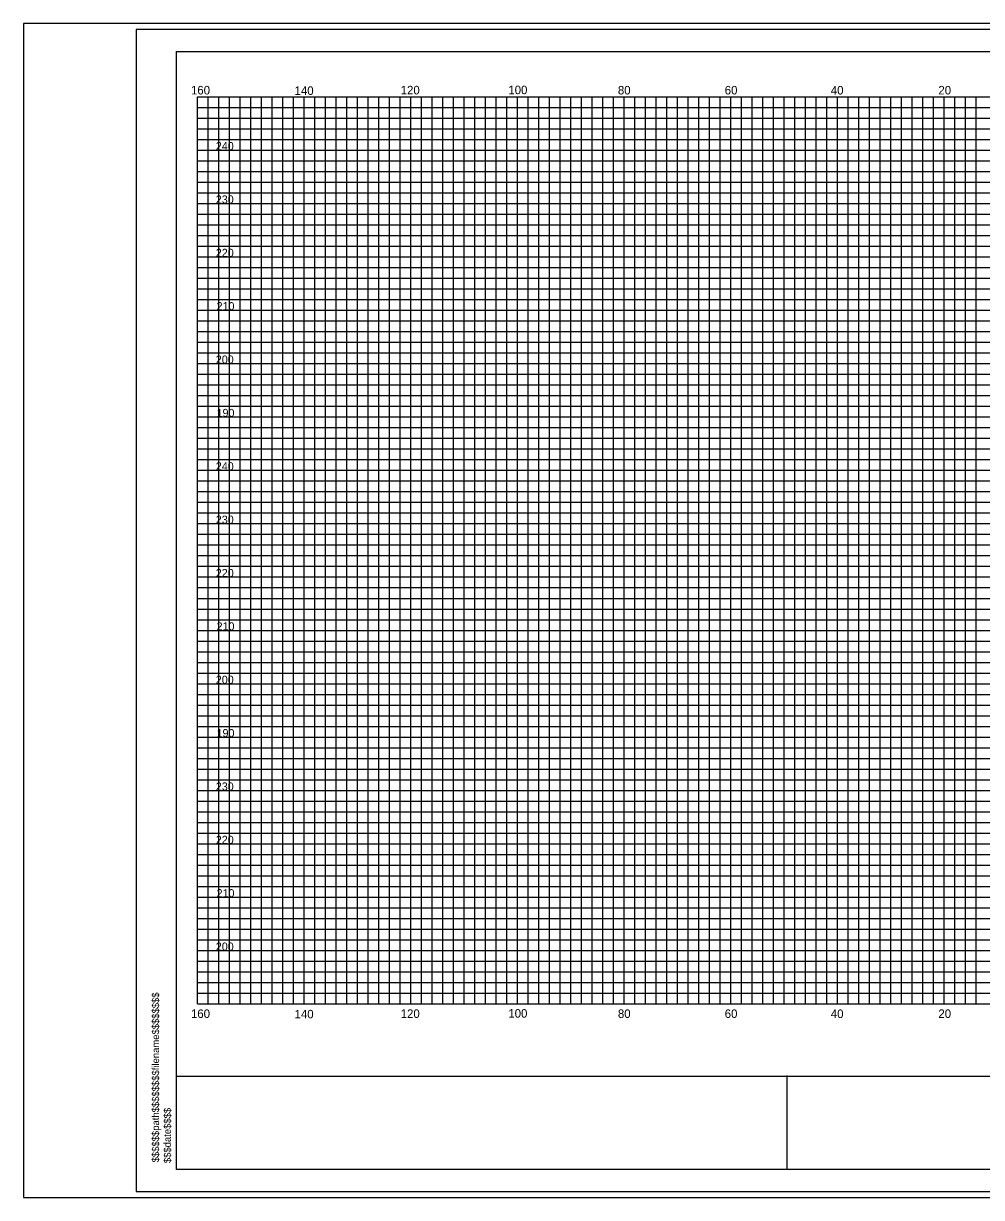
# Model space of a CAD drawing. Extents: x 967 to 1326, y 964 to 2304.
# Drawn here: x 967.4 to 1147, y 1243.7 to 1463.7 of the extents above; entities that cross this region are included whole.
import ezdxf

# ---------------------------------------------------------------- set-up
doc = ezdxf.new("R2010")
doc.units = 0
for name, color, linetype in [('Default', 7, 'Continuous'), ('RD_GPK_XS_Cell', 7, 'Continuous'), ('RD_PD_PaveShd', 7, 'Continuous'), ('RD_XS_ExGround', 7, 'Continuous'), ('RD_XS_ExPaveRet', 7, 'Continuous'), ('RD_XS_PaveOvlay', 7, 'Continuous'), ('RD_XS_TX_Elev_EX', 7, 'Continuous')]:
    doc.layers.add(name, color=color, linetype=linetype)

msp = doc.modelspace()

# ---------------------------------------------------------------- linework, layer by layer
at = {"layer": 'RD_GPK_XS_Cell'}
for p, q in [((1000, 1450), (1320, 1450)), ((1000, 1280), (1000, 1450)), ((1010, 1280), (1010, 1450)), ((1020, 1280), (1020, 1450)), ((1030, 1280), (1030, 1450)), ((1040, 1280), (1040, 1450)), ((1050, 1280), (1050, 1450)), ((1060, 1280), (1060, 1450)), ((1070, 1280), (1070, 1450)), ((1080, 1280), (1080, 1450)), ((1090, 1280), (1090, 1450)), ((1100, 1280), (1100, 1450)), ((1110, 1280), (1110, 1450)), ((1120, 1280), (1120, 1450)), ((1130, 1280), (1130, 1450)), ((1140, 1280), (1140, 1450)), ((1000, 1440), (1320, 1440)), ((1000, 1430), (1320, 1430)), ((1000, 1420), (1320, 1420)), ((1000, 1410), (1320, 1410)), ((1000, 1400), (1320, 1400)), ((1000, 1390), (1320, 1390)), ((1000, 1380), (1320, 1380)), ((1000, 1370), (1320, 1370)), ((1000, 1360), (1320, 1360)), ((1000, 1350), (1320, 1350)), ((1000, 1340), (1320, 1340)), ((1000, 1330), (1320, 1330)), ((1000, 1320), (1320, 1320)), ((1000, 1310), (1320, 1310)), ((1000, 1300), (1320, 1300)), ((1000, 1290), (1320, 1290)), ((1000, 1280), (1320, 1280))]:
    msp.add_line(p, q, dxfattribs=at)
at = {"layer": 'RD_PD_PaveShd'}
for p, q in [((996.11, 1248.98), (996.11, 1458.46)), ((996.11, 1458.46), (1323.89, 1458.46)), ((996.11, 1266.49), (1323.89, 1266.49)), ((1110.59, 1248.98), (1110.59, 1266.56)), ((1323.89, 1248.98), (996.11, 1248.98))]:
    msp.add_line(p, q, dxfattribs=at)
at = {"layer": 'RD_XS_ExGround'}
for p, q in [((1002, 1280), (1002, 1450)), ((1004, 1280), (1004, 1450)), ((1006, 1280), (1006, 1450)), ((1008, 1280), (1008, 1450)), ((1012, 1280), (1012, 1450)), ((1014, 1280), (1014, 1450)), ((1016, 1280), (1016, 1450)), ((1018, 1280), (1018, 1450)), ((1022, 1280), (1022, 1450)), ((1024, 1280), (1024, 1450)), ((1026, 1280), (1026, 1450)), ((1028, 1280), (1028, 1450)), ((1032, 1280), (1032, 1450)), ((1034, 1280), (1034, 1450)), ((1036, 1280), (1036, 1450)), ((1038, 1280), (1038, 1450)), ((1042, 1280), (1042, 1450)), ((1044, 1280), (1044, 1450)), ((1046, 1280), (1046, 1450)), ((1048, 1280), (1048, 1450)), ((1052, 1280), (1052, 1450)), ((1054, 1280), (1054, 1450)), ((1056, 1280), (1056, 1450)), ((1058, 1280), (1058, 1450)), ((1062, 1280), (1062, 1450)), ((1064, 1280), (1064, 1450)), ((1066, 1280), (1066, 1450)), ((1068, 1280), (1068, 1450)), ((1072, 1280), (1072, 1450)), ((1074, 1280), (1074, 1450)), ((1076, 1280), (1076, 1450)), ((1078, 1280), (1078, 1450)), ((1082, 1280), (1082, 1450)), ((1084, 1280), (1084, 1450)), ((1086, 1280), (1086, 1450)), ((1088, 1280), (1088, 1450)), ((1092, 1280), (1092, 1450)), ((1094, 1280), (1094, 1450)), ((1096, 1280), (1096, 1450)), ((1098, 1280), (1098, 1450)), ((1102, 1280), (1102, 1450)), ((1104, 1280), (1104, 1450)), ((1106, 1280), (1106, 1450)), ((1108, 1280), (1108, 1450)), ((1112, 1280), (1112, 1450)), ((1114, 1280), (1114, 1450)), ((1116, 1280), (1116, 1450)), ((1118, 1280), (1118, 1450)), ((1122, 1280), (1122, 1450)), ((1124, 1280), (1124, 1450)), ((1126, 1280), (1126, 1450)), ((1128, 1280), (1128, 1450)), ((1132, 1280), (1132, 1450)), ((1134, 1280), (1134, 1450)), ((1136, 1280), (1136, 1450)), ((1138, 1280), (1138, 1450)), ((1142, 1280), (1142, 1450)), ((1144, 1280), (1144, 1450)), ((1146, 1280), (1146, 1450)), ((1000, 1448), (1320, 1448)), ((1000, 1446), (1320, 1446)), ((1000, 1444), (1320, 1444)), ((1000, 1442), (1320, 1442)), ((1000, 1438), (1320, 1438)), ((1000, 1436), (1320, 1436)), ((1000, 1434), (1320, 1434)), ((1000, 1432), (1320, 1432)), ((1000, 1428), (1320, 1428)), ((1000, 1426), (1320, 1426)), ((1000, 1424), (1320, 1424)), ((1000, 1422), (1320, 1422)), ((1000, 1418), (1320, 1418)), ((1000, 1416), (1320, 1416)), ((1000, 1414), (1320, 1414)), ((1000, 1412), (1320, 1412)), ((1000, 1408), (1320, 1408)), ((1000, 1406), (1320, 1406)), ((1000, 1404), (1320, 1404)), ((1000, 1402), (1320, 1402)), ((1000, 1398), (1320, 1398)), ((1000, 1396), (1320, 1396)), ((1000, 1394), (1320, 1394)), ((1000, 1392), (1320, 1392)), ((1000, 1388), (1320, 1388)), ((1000, 1386), (1320, 1386)), ((1000, 1384), (1320, 1384)), ((1000, 1382), (1320, 1382)), ((1000, 1378), (1320, 1378)), ((1000, 1376), (1320, 1376)), ((1000, 1374), (1320, 1374)), ((1000, 1372), (1320, 1372)), ((1000, 1368), (1320, 1368)), ((1000, 1366), (1320, 1366)), ((1000, 1364), (1320, 1364)), ((1000, 1362), (1320, 1362)), ((1000, 1358), (1320, 1358)), ((1000, 1356), (1320, 1356)), ((1000, 1354), (1320, 1354)), ((1000, 1352), (1320, 1352)), ((1000, 1348), (1320, 1348)), ((1000, 1346), (1320, 1346)), ((1000, 1344), (1320, 1344)), ((1000, 1342), (1320, 1342)), ((1000, 1338), (1320, 1338)), ((1000, 1336), (1320, 1336)), ((1000, 1334), (1320, 1334)), ((1000, 1332), (1320, 1332)), ((1000, 1328), (1320, 1328)), ((1000, 1326), (1320, 1326)), ((1000, 1324), (1320, 1324)), ((1000, 1322), (1320, 1322)), ((1000, 1318), (1320, 1318)), ((1000, 1316), (1320, 1316)), ((1000, 1314), (1320, 1314)), ((1000, 1312), (1320, 1312)), ((1000, 1308), (1320, 1308)), ((1000, 1306), (1320, 1306)), ((1000, 1304), (1320, 1304)), ((1000, 1302), (1320, 1302)), ((1000, 1298), (1320, 1298)), ((1000, 1296), (1320, 1296)), ((1000, 1294), (1320, 1294)), ((1000, 1292), (1320, 1292)), ((1000, 1288), (1320, 1288)), ((1000, 1286), (1320, 1286)), ((1000, 1284), (1320, 1284)), ((1000, 1282), (1320, 1282))]:
    msp.add_line(p, q, dxfattribs=at)
at = {"layer": 'RD_XS_PaveOvlay'}
msp.add_lwpolyline([(967.41, 1243.72), (1326.28, 1243.72), (1326.28, 1463.72), (967.41, 1463.72)], close=True, dxfattribs=at)
at = {"layer": 'RD_XS_TX_Elev_EX'}
for points in [[(967.41, 1243.72), (1326.28, 1243.72), (1326.28, 1463.72), (967.41, 1463.72)], [(988.52, 1244.84), (1326.28, 1244.84), (1326.28, 1462.6), (988.52, 1462.6)]]:
    msp.add_lwpolyline(points, close=True, dxfattribs=at)

# ---------------------------------------------------------------- texts
at = {"layer": 'Default'}
for s, p in [('240', (1003.47, 1440)), ('230', (1003.47, 1430)), ('220', (1003.47, 1420)), ('210', (1003.61, 1410)), ('200', (1003.47, 1400)), ('190', (1003.61, 1390)), ('240', (1003.47, 1380)), ('230', (1003.47, 1370)), ('220', (1003.47, 1360)), ('210', (1003.61, 1350)), ('200', (1003.47, 1340)), ('190', (1003.61, 1330)), ('230', (1003.47, 1320)), ('220', (1003.47, 1310)), ('210', (1003.61, 1300)), ('200', (1003.47, 1290))]:
    msp.add_text(s, height=1.5, dxfattribs=at).set_placement(p)
for s, p in [('$$$$$$path$$$$$$$$filename$$$$$$$$', (992.83, 1250.31)), ('$$$date$$$$', (995.04, 1250.17))]:
    msp.add_text(s, height=1.3258, rotation=90, dxfattribs=at).set_placement(p)
at = {"layer": 'RD_XS_ExPaveRet'}
for s, p in [('160', (998.81, 1450.42)), ('120', (1038.12, 1450.43)), ('100', (1058.3, 1450.47)), ('80', (1078.84, 1450.42)), ('60', (1098.86, 1450.42)), ('40', (1118.75, 1450.41)), ('20', (1138.91, 1450.42)), ('140', (1018.23, 1450.34)), ('160', (998.81, 1277.37)), ('140', (1018.23, 1277.29)), ('120', (1038.12, 1277.38)), ('100', (1058.3, 1277.42)), ('80', (1078.84, 1277.37)), ('60', (1098.86, 1277.37)), ('40', (1118.75, 1277.36)), ('20', (1138.91, 1277.37))]:
    msp.add_text(s, height=1.6, dxfattribs=at).set_placement(p)

doc.saveas('drawing.dxf')
